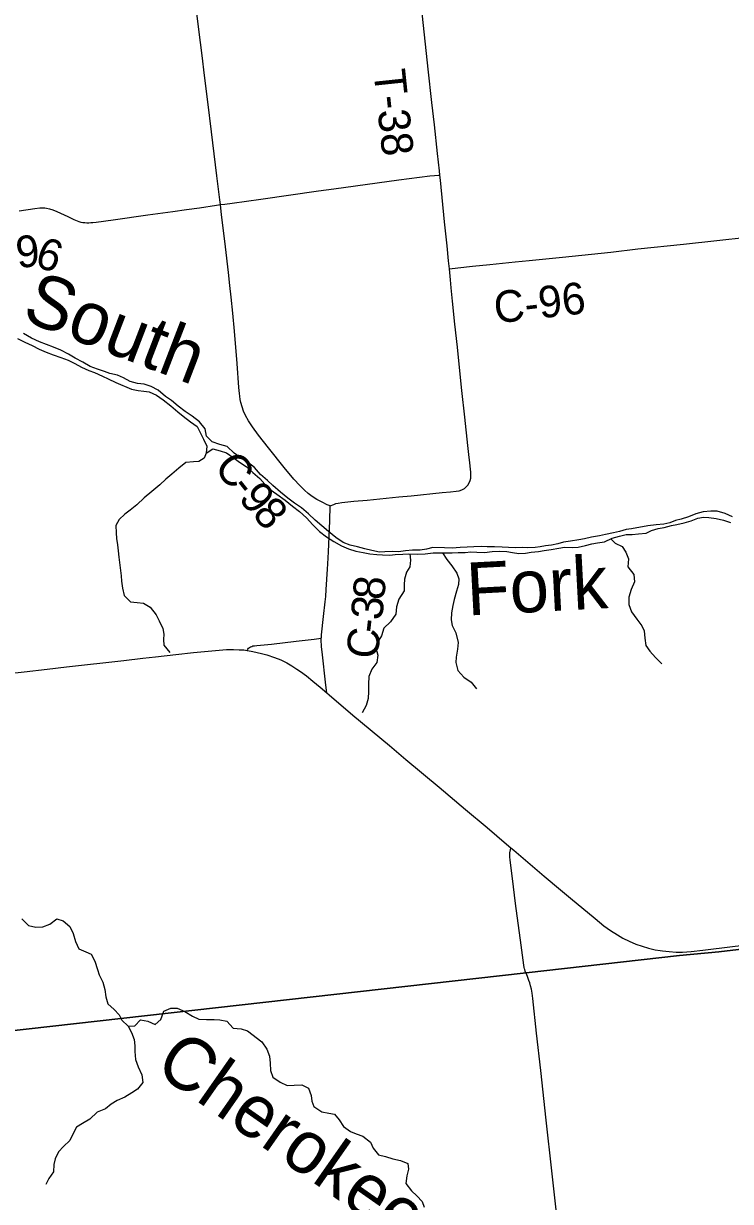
# Model space of a CAD drawing. Extents: x 0 to 34, y -5.4 to 22.
# Drawn here: x 3.849 to 5.117, y 18.333 to 20.446 of the extents above; entities that cross this region are included whole.
import ezdxf

# ---------------------------------------------------------------- set-up
doc = ezdxf.new("R2010")
doc.units = 0
for name, color, linetype in [('GM_X_County_Road', 7, 'Continuous'), ('GM_X_County_Road_Text', 7, 'Continuous'), ('GM_X_Minor_River', 7, 'Continuous'), ('GM_X_Minor_River_Text', 7, 'Continuous'), ('GM_X_Rail_Line', 7, 'Continuous'), ('GM_X_State_Route', 7, 'Continuous'), ('GM_X_Township_Road', 7, 'Continuous'), ('GM_X_Township_Road_Text', 7, 'Continuous')]:
    doc.layers.add(name, color=color, linetype=linetype)

msp = doc.modelspace()

# ---------------------------------------------------------------- linework, layer by layer
at = {"layer": 'GM_X_County_Road'}
for points in [[(4.6127, 20.0058), (4.6112, 20.0202), (4.6084, 20.0472), (4.604, 20.0905), (4.5963, 20.1653), (4.5953, 20.1744), (4.5946, 20.1819), (4.5913, 20.2128), (4.5856, 20.2647), (4.5812, 20.3042), (4.5747, 20.3641), (4.5646, 20.4593), (4.5568, 20.5328), (4.5477, 20.6224), (4.5419, 20.6793), (4.5398, 20.7021), (4.5389, 20.7111), (4.5382, 20.7168), (4.5376, 20.723), (4.5365, 20.7343), (4.5346, 20.7517), (4.5271, 20.8165), (4.5224, 20.8584), (4.5177, 20.9)], [(4.3986, 19.5807), (4.3934, 19.5829), (4.3844, 19.5872), (4.375, 19.5923), (4.3666, 19.5977), (4.3591, 19.6032), (4.3524, 19.609), (4.344, 19.6173), (4.3336, 19.6289), (4.3164, 19.6494), (4.288, 19.6848), (4.2701, 19.7079), (4.2596, 19.7226), (4.2524, 19.7335), (4.247, 19.7427), (4.2433, 19.7507), (4.2406, 19.7584), (4.2386, 19.7661), (4.2374, 19.7719), (4.2366, 19.7774), (4.2361, 19.7826), (4.235, 19.7929), (4.2316, 19.8363), (4.2269, 19.8944), (4.224, 19.9266), (4.2211, 19.955), (4.2188, 19.976), (4.2161, 19.9995), (4.2109, 20.0458), (4.2038, 20.1033), (4.2026, 20.1147), (4.2019, 20.1212), (4.2009, 20.1299), (4.1956, 20.173), (4.1858, 20.2518), (4.1794, 20.3055), (4.1734, 20.353), (4.169, 20.3887), (4.1631, 20.4356), (4.152, 20.5288)], [(4.6127, 20.0058), (4.6274, 20.0077), (4.6542, 20.0107), (4.6851, 20.0139), (4.7308, 20.0187), (4.7554, 20.0212), (4.8154, 20.0269), (4.902, 20.0362), (4.9508, 20.0418), (5.0323, 20.0506), (5.0923, 20.0569), (5.201, 20.0686), (5.3005, 20.0791), (5.3821, 20.0878), (5.4847, 20.0988), (5.5768, 20.1084), (5.6305, 20.114), (5.6639, 20.1176), (5.7554, 20.1273), (5.811, 20.1332), (5.8611, 20.1385), (5.8744, 20.1399)], [(4.3925, 19.2454), (4.3921, 19.2495), (4.3906, 19.2644), (4.3847, 19.3134), (4.3831, 19.3282), (4.3826, 19.3406), (4.3827, 19.3432), (4.3829, 19.3454), (4.3831, 19.348), (4.3833, 19.3496), (4.3869, 19.3825), (4.3898, 19.4084), (4.3907, 19.4182), (4.3918, 19.4307), (4.3942, 19.4672), (4.3948, 19.4769), (4.3959, 19.4984), (4.3965, 19.5119), (4.3982, 19.5538), (4.3986, 19.5807), (4.4053, 19.5835), (4.4089, 19.5848), (4.4129, 19.5859), (4.4196, 19.587), (4.4412, 19.5891), (4.4653, 19.5911), (4.5216, 19.5968), (4.5439, 19.5989), (4.5996, 19.6045), (4.6144, 19.6059), (4.6244, 19.6069), (4.63, 19.6079), (4.6348, 19.6094), (4.6394, 19.6118), (4.6429, 19.6147), (4.6459, 19.6181), (4.6482, 19.6219), (4.6498, 19.6261), (4.6508, 19.6305), (4.6513, 19.6356), (4.651, 19.6412), (4.6484, 19.6635), (4.648, 19.6678), (4.6456, 19.6888), (4.64, 19.7401), (4.635, 19.7877), (4.6299, 19.8353), (4.6268, 19.8656), (4.6223, 19.907), (4.6179, 19.9478), (4.6155, 19.972), (4.6143, 19.9863), (4.6127, 20.0058)], [(4.2499, 19.3215), (4.2511, 19.3236), (4.2525, 19.3254), (4.2538, 19.3265), (4.256, 19.3279), (4.2579, 19.3287), (4.2598, 19.3294), (4.2627, 19.3299), (4.2674, 19.3304), (4.2935, 19.3329), (4.3379, 19.3378), (4.37, 19.3416), (4.3827, 19.3432)]]:
    msp.add_lwpolyline(points, dxfattribs=at)
at = {"layer": 'GM_X_Minor_River'}
for points in [[(4.6566, 19.5071), (4.6445, 19.5066), (4.6319, 19.506), (4.6175, 19.5051), (4.6035, 19.5057), (4.5831, 19.506), (4.5717, 19.5032), (4.5599, 19.5011), (4.5466, 19.5016), (4.5337, 19.5003), (4.5212, 19.4982), (4.511, 19.4992), (4.4969, 19.4982), (4.4874, 19.498), (4.4735, 19.5005), (4.461, 19.5034), (4.4478, 19.507), (4.4346, 19.5102), (4.4221, 19.515), (4.409, 19.5243), (4.3959, 19.5347), (4.3836, 19.5448), (4.372, 19.5552), (4.3596, 19.5664), (4.3473, 19.5773), (4.3349, 19.5858), (4.3226, 19.5947), (4.3095, 19.6056), (4.296, 19.6172), (4.2863, 19.626), (4.2739, 19.6372), (4.2628, 19.6496), (4.2523, 19.6577), (4.2391, 19.6662), (4.2264, 19.6752), (4.2141, 19.6871), (4.2009, 19.6911), (4.1869, 19.6955), (4.1768, 19.7056), (4.1744, 19.7189), (4.1643, 19.7316), (4.1512, 19.7416), (4.1389, 19.7502), (4.1261, 19.7595), (4.1138, 19.7699), (4.1033, 19.7773), (4.0902, 19.7881), (4.0778, 19.7948), (4.0653, 19.7991), (4.0529, 19.8005), (4.04, 19.8037), (4.028, 19.8104), (4.0171, 19.8151), (4.0035, 19.8183), (3.9937, 19.8219), (3.9812, 19.8263), (3.9684, 19.831), (3.9553, 19.8384), (3.9414, 19.8455), (3.9294, 19.8529), (3.9158, 19.8599), (3.9027, 19.8658), (3.8898, 19.8702), (3.8774, 19.8753), (3.8627, 19.8816), (3.8484, 19.8898)], [(3.8381, 19.8809), (3.8512, 19.8742), (3.864, 19.8683), (3.8768, 19.8621), (3.8892, 19.8566), (3.9017, 19.8518), (3.9156, 19.847), (3.9288, 19.8419), (3.9408, 19.836), (3.9525, 19.8294), (3.966, 19.8239), (3.9758, 19.8199), (3.9905, 19.8132), (4.0007, 19.8089), (4.0142, 19.8022), (4.0421, 19.7904), (4.0542, 19.7879), (4.0644, 19.7866), (4.0742, 19.7853), (4.0874, 19.7791), (4.0994, 19.7709), (4.1129, 19.7604), (4.1252, 19.7492), (4.1353, 19.7415), (4.1481, 19.7318), (4.16, 19.7229), (4.1667, 19.7103), (4.1715, 19.7007), (4.1773, 19.6877), (4.176, 19.6752), (4.1882, 19.6834), (4.2011, 19.6794), (4.2128, 19.6758), (4.2263, 19.6664), (4.236, 19.6591), (4.248, 19.6513), (4.26, 19.6409), (4.2723, 19.6297), (4.2813, 19.62), (4.291, 19.6104), (4.3033, 19.6015), (4.318, 19.591), (4.3311, 19.5802), (4.3434, 19.5705), (4.3561, 19.5593), (4.3677, 19.5466), (4.3796, 19.5346), (4.392, 19.5253), (4.4051, 19.5168), (4.419, 19.509), (4.4318, 19.5034), (4.4447, 19.4998), (4.4579, 19.497), (4.4696, 19.4949), (4.4825, 19.4935), (4.4923, 19.493), (4.5055, 19.4924), (4.515, 19.4934), (4.5291, 19.4943), (4.5397, 19.4945), (4.5545, 19.4939), (4.5693, 19.4948), (4.5837, 19.4965), (4.5947, 19.4963)], [(4.176, 19.6752), (4.1728, 19.6665), (4.1633, 19.6602), (4.1538, 19.66), (4.1401, 19.6583), (4.1275, 19.6486), (4.1144, 19.6374), (4.104, 19.6285), (4.0933, 19.6188), (4.0787, 19.6065), (4.0653, 19.5953), (4.0522, 19.5826), (4.0399, 19.573), (4.0303, 19.5659), (4.0203, 19.5566), (4.0141, 19.5453), (4.0147, 19.5327), (4.0156, 19.5225), (4.0174, 19.5107), (4.0187, 19.5), (4.0197, 19.489), (4.0214, 19.4746), (4.0227, 19.465), (4.0237, 19.4552), (4.0247, 19.4457), (4.026, 19.4331), (4.0289, 19.4198), (4.0404, 19.4086), (4.0525, 19.4073), (4.0639, 19.4063), (4.0759, 19.3989), (4.0863, 19.3851), (4.0918, 19.3748), (4.0984, 19.3606), (4.1002, 19.3507), (4.1, 19.3409), (4.1006, 19.3306), (4.1114, 19.3179)], [(5.1205, 19.5614), (5.107, 19.5669), (5.093, 19.571), (5.0813, 19.5715), (5.068, 19.5698), (5.0543, 19.5662), (5.0413, 19.5611), (5.0284, 19.5572), (5.0181, 19.5543), (5.0078, 19.5503), (4.9971, 19.5482), (4.9835, 19.5465), (4.9683, 19.5448), (4.9588, 19.5434), (4.9485, 19.5413), (4.939, 19.5396), (4.9295, 19.5382), (4.9174, 19.5346), (4.9071, 19.5325), (4.8926, 19.5293), (4.882, 19.5272), (4.8676, 19.5244), (4.855, 19.5215), (4.8448, 19.5198), (4.8299, 19.5173), (4.817, 19.5157), (4.8071, 19.5128), (4.7957, 19.5103), (4.7851, 19.5089), (4.7756, 19.5072), (4.7661, 19.5062), (4.7528, 19.5056), (4.7434, 19.5058), (4.732, 19.5056), (4.7184, 19.5062), (4.707, 19.5064), (4.6934, 19.5073), (4.6801, 19.5072), (4.6695, 19.5077), (4.6566, 19.5071)], [(4.5947, 19.4963), (4.6049, 19.4966), (4.6178, 19.4967), (4.6284, 19.497), (4.6409, 19.4971), (4.6508, 19.4981), (4.6618, 19.498), (4.6758, 19.4974), (4.6891, 19.4987), (4.7023, 19.4996), (4.7156, 19.499), (4.7258, 19.497), (4.7371, 19.4956), (4.7489, 19.4962), (4.7592, 19.4976), (4.7721, 19.4989), (4.7827, 19.5006), (4.7949, 19.5027), (4.8089, 19.5051), (4.8188, 19.5065), (4.8339, 19.5063), (4.8438, 19.5069), (4.8567, 19.5097), (4.8681, 19.5126), (4.878, 19.5143), (4.8909, 19.5164), (4.9047, 19.523), (4.9176, 19.5266), (4.9298, 19.5295), (4.9404, 19.5297), (4.9518, 19.5306), (4.9654, 19.5319), (4.975, 19.5364), (4.9872, 19.54), (4.9978, 19.5417), (5.0107, 19.5453), (5.0203, 19.5474), (5.0339, 19.5506), (5.0461, 19.5538), (5.0579, 19.5586), (5.0682, 19.5607), (5.078, 19.5602), (5.0913, 19.5581), (5.1045, 19.5552), (5.1169, 19.5509)], [(4.9019, 19.5217), (4.9098, 19.5138), (4.9223, 19.5076), (4.9293, 19.498), (4.934, 19.4857), (4.9327, 19.4717), (4.9435, 19.4579), (4.9444, 19.4446), (4.9385, 19.4306), (4.9345, 19.417), (4.9343, 19.4038), (4.9394, 19.3904), (4.9487, 19.3777), (4.958, 19.3658), (4.962, 19.3563), (4.9633, 19.3433), (4.965, 19.3304), (4.9721, 19.32), (4.9825, 19.3085), (4.9933, 19.2973)], [(4.5413, 19.4945), (4.5429, 19.4831), (4.5416, 19.4717), (4.5354, 19.4616), (4.5318, 19.4491), (4.5313, 19.4389), (4.5315, 19.4286), (4.5218, 19.4136), (4.5178, 19.3996), (4.5164, 19.3863), (4.5068, 19.3728), (4.4952, 19.3612), (4.4908, 19.3477), (4.4842, 19.3371), (4.4807, 19.3262), (4.4839, 19.3128), (4.4821, 19.2996), (4.4736, 19.2876), (4.4681, 19.2744), (4.4675, 19.2607), (4.4677, 19.2478), (4.4671, 19.2353), (4.4632, 19.2228), (4.4561, 19.2097)], [(4.5999, 19.4965), (4.6077, 19.4844), (4.617, 19.4732), (4.6259, 19.4602), (4.6296, 19.4499), (4.629, 19.44), (4.6255, 19.4279), (4.6211, 19.4128), (4.619, 19.4018), (4.6161, 19.389), (4.6156, 19.3765), (4.6173, 19.3662), (4.6239, 19.3528), (4.6282, 19.3356), (4.6269, 19.3239), (4.6248, 19.3095), (4.6243, 19.2996), (4.6278, 19.2852), (4.6386, 19.2732), (4.6514, 19.2647), (4.6614, 19.2524)], [(3.8455, 18.8396), (3.8578, 18.828), (3.871, 18.8251), (3.8835, 18.8253), (3.8961, 18.8303), (3.9083, 18.8396), (3.92, 18.836), (3.9316, 18.8263), (3.9378, 18.8133), (3.9417, 18.7992), (3.9476, 18.7862), (3.9603, 18.7807), (3.9701, 18.7764), (3.9767, 18.7641), (3.9814, 18.7492), (3.9846, 18.7393), (3.9912, 18.7263), (3.9944, 18.713), (3.9961, 18.7001), (4, 18.6871), (4.0112, 18.6774), (4.0201, 18.6674), (4.0253, 18.6578), (4.0365, 18.6474), (4.0486, 18.648), (4.0586, 18.6588), (4.0718, 18.6563), (4.0849, 18.65), (4.0949, 18.6593)], [(4.0949, 18.6593), (4.1001, 18.674), (4.1131, 18.6795), (4.1244, 18.6797), (4.1383, 18.6737), (4.1518, 18.6652), (4.1631, 18.66), (4.1771, 18.6594), (4.1907, 18.6592), (4.2005, 18.6586), (4.2133, 18.6561), (4.2249, 18.6438), (4.2389, 18.6428), (4.2505, 18.6388), (4.2759, 18.619), (4.2852, 18.606), (4.2899, 18.5934), (4.2912, 18.5808), (4.2917, 18.5679), (4.2961, 18.5557), (4.3092, 18.5468), (4.3216, 18.5409), (4.3341, 18.5414), (4.3481, 18.5423), (4.3597, 18.536), (4.3648, 18.5227), (4.3661, 18.5128), (4.3694, 18.5033), (4.3836, 18.4935), (4.3964, 18.491), (4.4062, 18.4894), (4.4148, 18.4793), (4.4229, 18.4671), (4.4352, 18.4585), (4.4454, 18.4542), (4.4574, 18.4502), (4.4712, 18.4393), (4.4756, 18.4286), (4.4853, 18.4167), (4.4981, 18.4134), (4.5109, 18.4094), (4.5248, 18.4065), (4.538, 18.401), (4.5389, 18.3907), (4.5361, 18.3786), (4.5347, 18.365), (4.5447, 18.3519), (4.5544, 18.3431), (4.5637, 18.333), (4.5673, 18.3223)], [(4.0365, 18.6474), (4.0423, 18.6359), (4.047, 18.6233), (4.0484, 18.6123), (4.0486, 18.6017), (4.0498, 18.5872), (4.0545, 18.5743), (4.0611, 18.5597), (4.0624, 18.5464), (4.0531, 18.5341), (4.0428, 18.5278), (4.0306, 18.5201), (4.0164, 18.5138), (4.0057, 18.5072), (3.9958, 18.499), (3.9809, 18.4928), (3.9678, 18.4805), (3.9544, 18.4724), (3.9434, 18.4658), (3.9363, 18.4522), (3.9316, 18.4421), (3.9201, 18.4313), (3.9116, 18.4216), (3.9053, 18.4095), (3.9033, 18.3993), (3.9027, 18.3861), (3.8941, 18.3737), (3.8887, 18.3635)]]:
    msp.add_lwpolyline(points, dxfattribs=at)
at = {"layer": 'GM_X_Rail_Line'}
msp.add_lwpolyline([(8.9, 19.2127), (8.9, 20.9), (3.5133, 20.9), (3.5122, 20.8763), (3.4778, 20.1697), (3.46, 19.8188), (3.4303, 19.2337), (3.4301, 19.2311), (3.4297, 19.2264), (3.3865, 18.7781), (3.3669, 18.5872), (3.5131, 18.6037), (4.7505, 18.7432), (5.0255, 18.7742), (5.096, 18.7806), (5.378, 18.814), (5.7313, 18.8595), (5.7334, 18.8597), (6.0045, 18.8908), (6.4496, 18.9373), (6.6792, 18.9603), (6.9054, 18.9823), (7.2315, 19.0156), (8.5201, 19.1691)], close=True, dxfattribs=at)
msp.add_lwpolyline([(8.9, 15.5944), (8.9, 19.2127), (8.5201, 19.1691), (7.2315, 19.0156), (6.9054, 18.9823), (6.6792, 18.9603), (6.4496, 18.9373), (6.0045, 18.8908), (5.7334, 18.8597), (5.7313, 18.8595), (5.378, 18.814), (5.096, 18.7806), (5.0255, 18.7742), (4.7505, 18.7432), (3.5131, 18.6037), (3.3669, 18.5872), (3.3607, 18.5226), (3.3599, 18.5136), (3.2432, 17.2942), (3.13, 16.1326)], dxfattribs=at)
at = {"layer": 'GM_X_State_Route'}
for points in [[(3.8171, 19.2792), (3.8498, 19.283), (3.8911, 19.2878), (3.9257, 19.2917), (4.0288, 19.3034), (4.0628, 19.3075), (4.0856, 19.3099), (4.1221, 19.3139), (4.1535, 19.3176), (4.1993, 19.322), (4.2129, 19.3229), (4.2252, 19.3229), (4.2357, 19.3227), (4.241, 19.3224), (4.2436, 19.3222), (4.2499, 19.3215), (4.2572, 19.3202), (4.2653, 19.3185), (4.2779, 19.3155), (4.2852, 19.3135), (4.2987, 19.3089), (4.31, 19.3043), (4.3208, 19.299), (4.3301, 19.2935), (4.3391, 19.2879), (4.3457, 19.2835), (4.3562, 19.2757), (4.3678, 19.266), (4.3805, 19.2554), (4.3925, 19.2454), (4.3969, 19.2417), (4.4396, 19.2055), (4.5051, 19.1507), (4.5347, 19.1259), (4.5941, 19.0759), (4.6416, 19.0358), (4.6804, 19.0038), (4.715, 18.9736), (4.7229, 18.9672), (4.7283, 18.9628), (4.7827, 18.9162), (4.8121, 18.8917), (4.8297, 18.8768), (4.8739, 18.8402), (4.8896, 18.8276), (4.9016, 18.8187), (4.914, 18.8109), (4.9239, 18.8051), (4.9348, 18.7997), (4.9471, 18.7944), (4.9584, 18.7906), (4.9699, 18.7873), (4.9819, 18.7845), (4.9909, 18.7831)], [(4.9909, 18.7831), (4.9947, 18.7825), (5.0069, 18.7811), (5.0191, 18.7803), (5.0304, 18.7803), (5.0463, 18.7815), (5.0672, 18.7836), (5.1201, 18.7901), (5.1708, 18.7963), (5.319, 18.8147), (5.3771, 18.8215), (5.3952, 18.8236), (5.4492, 18.8298), (5.5498, 18.8408), (5.5998, 18.8465), (5.6652, 18.8537), (5.7004, 18.8576)]]:
    msp.add_lwpolyline(points, dxfattribs=at)
at = {"layer": 'GM_X_Township_Road'}
for points in [[(4.1162, 20.109), (4.1409, 20.1124), (4.1645, 20.1155), (4.195, 20.1201), (4.2019, 20.1212), (4.21, 20.1223), (4.2227, 20.1241), (4.2741, 20.1312), (4.3775, 20.1457), (4.4053, 20.1497), (4.5221, 20.1659), (4.5772, 20.1729), (4.5859, 20.1737), (4.5931, 20.1742), (4.5953, 20.1744)], [(3.8408, 20.1099), (3.869, 20.1143), (3.8777, 20.1152), (3.8832, 20.1155), (3.8869, 20.1154), (3.8901, 20.115), (3.8955, 20.1138), (3.9015, 20.112), (3.9084, 20.1092), (3.928, 20.0997), (3.9392, 20.0944), (3.9479, 20.0911), (3.9516, 20.09), (3.9552, 20.0893), (3.9588, 20.0889), (3.962, 20.0887), (3.9657, 20.0886), (3.9697, 20.0889), (3.9731, 20.0892), (3.9792, 20.0899), (4.0094, 20.0942), (4.0716, 20.1029), (4.1162, 20.109)], [(4.7475, 18.7502), (4.7469, 18.7528), (4.7462, 18.7568), (4.7413, 18.7925), (4.7313, 18.8676), (4.7273, 18.8972), (4.7213, 18.9459), (4.7208, 18.9503), (4.7207, 18.9547), (4.7212, 18.9584), (4.7222, 18.9634), (4.7229, 18.9672)], [(4.7513, 18.7391), (4.7487, 18.7458), (4.7478, 18.749), (4.7475, 18.7502)], [(4.8094, 18.2692), (4.796, 18.3877), (4.786, 18.4785), (4.7763, 18.568), (4.769, 18.6347), (4.7625, 18.6971), (4.7612, 18.7063), (4.7598, 18.7136), (4.7582, 18.7195), (4.7566, 18.7249), (4.7552, 18.729), (4.7524, 18.7363), (4.7513, 18.7391)]]:
    msp.add_lwpolyline(points, dxfattribs=at)

# ---------------------------------------------------------------- texts
at = {"layer": 'GM_X_County_Road_Text'}
for s, height, rotation, p in [('C-96', 0.05682, 6.53, (4.6956, 19.9079)), ('C', 0.0568, 308.2947, (4.1885, 19.6498)), ('-', 0.0568, 308.5124, (4.2176, 19.613)), ('9', 0.0568, 309.3481, (4.2327, 19.5941)), ('8', 0.0568, 312.4352, (4.2571, 19.5645)), ('8', 0.0568, 85.1722, (4.4955, 19.4107)), ('3', 0.0568, 83.6893, (4.4915, 19.3743)), ('C', 0.0568, 83.2008, (4.4832, 19.3043)), ('-', 0.0568, 83.3192, (4.4888, 19.3507))]:
    msp.add_text(s, height=height, rotation=rotation, dxfattribs=at).set_placement(p)
at = {"layer": 'GM_X_Minor_River_Text'}
for s, height, rotation, p in [('South', 0.0947, 339.028, (3.8428, 19.9156)), ('Fork', 0.09471, 3.0272, (4.6455, 19.384)), ('Cherokee', 0.09471, 325.0277, (4.0804, 18.5678))]:
    msp.add_text(s, height=height, rotation=rotation, dxfattribs=at).set_placement(p)
at = {"layer": 'GM_X_Township_Road_Text'}
for s, height, rotation, p in [('T-38', 0.05682, 276.0282, (4.4763, 20.3614)), ('9', 0.0568, 6.6183, (3.8382, 20.007)), ('6', 0.0568, 340.6122, (3.8663, 20.0118))]:
    msp.add_text(s, height=height, rotation=rotation, dxfattribs=at).set_placement(p)

doc.saveas('drawing.dxf')
